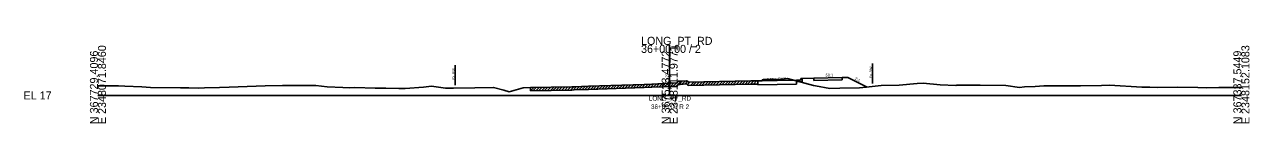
# Model space of a CAD drawing. Extents: x 974 to 2350744, y -10 to 368509.
# Drawn here: x 974.3 to 1402.8, y 990.3 to 1020.4 of the extents above; entities that cross this region are included whole.
import ezdxf

# ---------------------------------------------------------------- set-up
doc = ezdxf.new("R2010")
doc.units = 0
for name, color, linetype in [('RD_GPK_XS_Cell', 7, 'Continuous'), ('RD_XS_Base', 7, 'Continuous'), ('RD_XS_CurbBase', 7, 'Continuous'), ('RD_XS_CurbFront', 7, 'Continuous'), ('RD_XS_CurbTop', 7, 'Continuous'), ('RD_XS_EarthShd', 7, 'Continuous'), ('RD_XS_ExGround', 7, 'Continuous'), ('RD_XS_ExPaveRet', 7, 'Continuous'), ('RD_XS_ExRW', 7, 'Continuous'), ('RD_XS_Pave', 7, 'Continuous'), ('RD_XS_SW', 7, 'Continuous'), ('RD_XS_SWbase', 7, 'Continuous'), ('RD_XS_TieSlope', 7, 'Continuous'), ('RD_XS_TX_Elev_EX', 7, 'Continuous'), ('RD_XS_TX_Slope', 7, 'Continuous'), ('RD_XS_TX_Station', 7, 'Continuous')]:
    doc.layers.add(name, color=color, linetype=linetype)

msp = doc.modelspace()

# ---------------------------------------------------------------- linework, layer by layer
at = {"layer": 'RD_GPK_XS_Cell'}
for p, q in [((1200, 1000), (1200, 1017.61)), ((1000, 1000), (1200, 1000)), ((1200, 1000), (1400, 1000))]:
    msp.add_line(p, q, dxfattribs=at)
at = {"layer": 'RD_XS_Base'}
for p, q in [((1230.85, 1003.68), (1230.85, 1005.08)), ((1230.85, 1003.68), (1244.38, 1003.92)), ((1244.38, 1005.33), (1244.38, 1003.92))]:
    msp.add_line(p, q, dxfattribs=at)
at = {"layer": 'RD_XS_CurbBase'}
for p, q in [((1245.8, 1004.89), (1244.38, 1004.87)), ((1246.38, 1004.89), (1245.8, 1004.89)), ((1246.38, 1005.89), (1246.38, 1004.89))]:
    msp.add_line(p, q, dxfattribs=at)
at = {"layer": 'RD_XS_CurbFront'}
msp.add_line((1244.38, 1004.87), (1244.38, 1005.31), dxfattribs=at)
at = {"layer": 'RD_XS_CurbTop'}
for p, q in [((1244.38, 1005.31), (1245.8, 1005.39)), ((1244.38, 1005.33), (1244.38, 1005.31)), ((1245.8, 1005.39), (1245.88, 1005.89)), ((1245.88, 1005.89), (1246.38, 1005.89))]:
    msp.add_line(p, q, dxfattribs=at)
at = {"layer": 'RD_XS_EarthShd'}
for p, q in [((1246.38, 1005.89), (1250.38, 1006.03)), ((1260.38, 1006.23), (1262.38, 1006.27))]:
    msp.add_line(p, q, dxfattribs=at)
at = {"layer": 'RD_XS_ExGround'}
msp.add_lwpolyline([(1000, 1003.39), (1007.23, 1003.29), (1009.45, 1003.25), (1015.32, 1003.03), (1018.43, 1002.8), (1028.92, 1002.61), (1029.86, 1002.63), (1031.8, 1002.62), (1035.01, 1002.57), (1037.28, 1002.63), (1042.57, 1002.75), (1045.95, 1002.86), (1058.49, 1003.31), (1064.61, 1003.44), (1065.32, 1003.45), (1067.02, 1003.46), (1073.03, 1003.43), (1075.46, 1003.47), (1076.22, 1003.5), (1080.23, 1003.05), (1085.64, 1002.75), (1087.88, 1002.7), (1089.89, 1002.71), (1097, 1002.5), (1100.76, 1002.52), (1105.25, 1002.42), (1107.49, 1002.4), (1113.91, 1002.84), (1116.64, 1003.24), (1120.79, 1002.65), (1121.58, 1002.58), (1124.41, 1002.55), (1131.82, 1002.68), (1138.42, 1002.77), (1142.01, 1001.82), (1143.83, 1001.3), (1148.79, 1002.65), (1151.27, 1002.8), (1165.79, 1003.03), (1166.65, 1003.04), (1171.65, 1003.21), (1191.1, 1003.86), (1193.8, 1003.97), (1198.01, 1004.19), (1200, 1004.29), (1202.61, 1004.42), (1202.76, 1004.77), (1203.11, 1004.92), (1203.72, 1004.98), (1205.93, 1005.14), (1206.28, 1004.99), (1206.43, 1004.64), (1228.45, 1005.05), (1230.85, 1005.08), (1232.35, 1005.08), (1232.5, 1005.44), (1232.85, 1005.59), (1237.51, 1005.59), (1237.85, 1005.59), (1241.27, 1005.87), (1250.37, 1003.49), (1251, 1003.38), (1256.05, 1002.41), (1259.56, 1002.49), (1266.45, 1002.61), (1268.78, 1002.84), (1273.96, 1003.52), (1280.3, 1003.58), (1286.61, 1004.19), (1288.63, 1004.23), (1294.59, 1003.73), (1300.12, 1003.51), (1300.51, 1003.55), (1302, 1003.54), (1308.65, 1003.55), (1317.63, 1003.49), (1322.34, 1002.82), (1324.17, 1002.95), (1327.81, 1003.17), (1330.93, 1003.34), (1336.12, 1003.34), (1340.23, 1003.35), (1343.71, 1003.37), (1351.06, 1003.5), (1353.89, 1003.53), (1365.15, 1002.85), (1367.92, 1002.84), (1370.77, 1002.78), (1377.65, 1002.9), (1384.71, 1002.81), (1387.89, 1002.69), (1392.06, 1002.82), (1399.17, 1002.75), (1400, 1002.73)], dxfattribs=at)
at = {"layer": 'RD_XS_ExPaveRet'}
for p, q in [((1151.27, 1001.65), (1152.43, 1002.81)), ((1151.27, 1001.65), (1151.27, 1002.8)), ((1152.27, 1001.67), (1153.43, 1002.83)), ((1153.27, 1001.68), (1154.43, 1002.85)), ((1154.27, 1001.7), (1155.43, 1002.86)), ((1155.27, 1001.72), (1156.43, 1002.88)), ((1156.27, 1001.73), (1157.43, 1002.89)), ((1157.27, 1001.75), (1158.43, 1002.91)), ((1158.27, 1001.76), (1159.43, 1002.93)), ((1159.27, 1001.78), (1160.43, 1002.94)), ((1160.27, 1001.8), (1161.43, 1002.96)), ((1161.27, 1001.81), (1162.43, 1002.97)), ((1162.27, 1001.83), (1163.43, 1002.99)), ((1163.27, 1001.84), (1164.43, 1003)), ((1164.27, 1001.86), (1165.43, 1003.02)), ((1165.27, 1001.88), (1166.43, 1003.04)), ((1166.27, 1001.89), (1167.45, 1003.07)), ((1167.27, 1001.92), (1168.45, 1003.1)), ((1168.27, 1001.95), (1169.45, 1003.14)), ((1169.27, 1001.99), (1170.45, 1003.17)), ((1170.27, 1002.02), (1171.45, 1003.2)), ((1171.27, 1002.05), (1172.45, 1003.24)), ((1172.27, 1002.09), (1173.45, 1003.27)), ((1173.27, 1002.12), (1174.45, 1003.3)), ((1174.27, 1002.15), (1175.45, 1003.34)), ((1175.27, 1002.19), (1176.45, 1003.37)), ((1176.27, 1002.22), (1177.45, 1003.4)), ((1177.27, 1002.25), (1178.45, 1003.44)), ((1178.27, 1002.29), (1179.45, 1003.47)), ((1179.27, 1002.32), (1180.45, 1003.5)), ((1180.27, 1002.35), (1181.45, 1003.54)), ((1181.27, 1002.39), (1182.45, 1003.57)), ((1182.27, 1002.42), (1183.45, 1003.6)), ((1183.27, 1002.46), (1184.45, 1003.64)), ((1184.27, 1002.49), (1185.45, 1003.67)), ((1185.27, 1002.52), (1186.45, 1003.71)), ((1186.27, 1002.56), (1187.45, 1003.74)), ((1187.27, 1002.59), (1188.45, 1003.77)), ((1188.27, 1002.62), (1189.45, 1003.81)), ((1189.27, 1002.66), (1190.45, 1003.84)), ((1190.27, 1002.69), (1191.46, 1003.87)), ((1191.1, 1002.72), (1193.8, 1002.83)), ((1191.27, 1002.72), (1192.46, 1003.91)), ((1192.27, 1002.76), (1193.46, 1003.95)), ((1193.27, 1002.8), (1194.47, 1004)), ((1193.8, 1002.83), (1198.01, 1003.05)), ((1194.27, 1002.85), (1195.48, 1004.06)), ((1195.27, 1002.9), (1196.48, 1004.11)), ((1196.27, 1002.96), (1197.48, 1004.16)), ((1197.27, 1003.01), (1198.48, 1004.21)), ((1198.01, 1003.05), (1200, 1003.15)), ((1198.27, 1003.06), (1199.47, 1004.26)), ((1199.27, 1003.11), (1200.47, 1004.31)), ((1200, 1003.15), (1202.61, 1003.27)), ((1200.27, 1003.16), (1201.47, 1004.36)), ((1201.27, 1003.21), (1202.47, 1004.41)), ((1202.27, 1003.26), (1204.02, 1005)), ((1202.61, 1003.27), (1202.76, 1003.62)), ((1202.76, 1003.62), (1203.11, 1003.77)), ((1203.11, 1003.77), (1203.72, 1003.84)), ((1203.27, 1003.79), (1204.52, 1005.04)), ((1203.72, 1003.84), (1205.93, 1003.99)), ((1204.27, 1003.88), (1205.5, 1005.11)), ((1205.27, 1003.95), (1206.29, 1004.96)), ((1205.93, 1003.99), (1206.28, 1003.84)), ((1206.27, 1003.85), (1207.07, 1004.65)), ((1206.28, 1003.84), (1206.43, 1003.49)), ((1206.43, 1003.49), (1228.45, 1003.9)), ((1207.27, 1003.51), (1208.43, 1004.67)), ((1208.27, 1003.53), (1209.43, 1004.69)), ((1209.27, 1003.55), (1210.43, 1004.71)), ((1210.27, 1003.57), (1211.43, 1004.73)), ((1211.27, 1003.58), (1212.43, 1004.75)), ((1212.27, 1003.6), (1213.43, 1004.77)), ((1213.27, 1003.62), (1214.43, 1004.79)), ((1214.27, 1003.64), (1215.43, 1004.8)), ((1215.27, 1003.66), (1216.43, 1004.82)), ((1216.27, 1003.68), (1217.43, 1004.84)), ((1217.27, 1003.7), (1218.43, 1004.86)), ((1218.27, 1003.71), (1219.43, 1004.88)), ((1219.27, 1003.73), (1220.43, 1004.9)), ((1220.27, 1003.75), (1221.43, 1004.92)), ((1221.27, 1003.77), (1222.43, 1004.94)), ((1222.27, 1003.79), (1223.43, 1004.95)), ((1223.27, 1003.81), (1224.43, 1004.97)), ((1224.27, 1003.83), (1225.43, 1004.99)), ((1225.27, 1003.84), (1226.43, 1005.01)), ((1226.27, 1003.86), (1227.43, 1005.03)), ((1227.27, 1003.88), (1228.43, 1005.05)), ((1228.27, 1003.9), (1229.43, 1005.06)), ((1228.45, 1003.9), (1230.85, 1003.94)), ((1229.27, 1003.92), (1230.43, 1005.08)), ((1230.85, 1005.08), (1230.85, 1003.94)), ((1151.27, 1001.65), (1165.79, 1001.88)), ((1165.79, 1001.88), (1166.65, 1001.9)), ((1166.65, 1001.9), (1171.65, 1002.07)), ((1171.65, 1002.07), (1191.1, 1002.72))]:
    msp.add_line(p, q, dxfattribs=at)
at = {"layer": 'RD_XS_ExRW'}
for p, q in [((1125, 1003.56), (1125, 1010.56)), ((1271, 1004.13), (1271, 1011.13))]:
    msp.add_line(p, q, dxfattribs=at)
at = {"layer": 'RD_XS_Pave'}
msp.add_line((1230.85, 1005.08), (1244.38, 1005.33), dxfattribs=at)
at = {"layer": 'RD_XS_SW'}
msp.add_line((1250.38, 1006.03), (1260.38, 1006.23), dxfattribs=at)
at = {"layer": 'RD_XS_SWbase'}
for p, q in [((1250.38, 1006.03), (1250.38, 1005.19)), ((1250.38, 1005.19), (1260.38, 1005.39)), ((1260.38, 1005.39), (1260.38, 1006.23))]:
    msp.add_line(p, q, dxfattribs=at)
at = {"layer": 'RD_XS_TieSlope'}
msp.add_line((1262.38, 1006.27), (1269.14, 1002.89), dxfattribs=at)

# ---------------------------------------------------------------- texts
at = {"layer": 'RD_GPK_XS_Cell'}
for s, p in [('LONG_PT_RD', (1190, 1017.61)), ('36+00.00 / 2', (1190, 1014.81)), ('EL 17', (974, 998.6))]:
    msp.add_text(s, height=2.8, dxfattribs=at).set_placement(p)
for s, p in [('E 2348071.8460', (1002.8, 990)), ('E 2348111.9771', (1202.8, 990)), ('E 2348152.1083', (1402.8, 990)), ('N 367729.4096', (1000, 990)), ('N 367533.4772', (1200, 990)), ('N 367337.5449', (1400, 990))]:
    msp.add_text(s, height=2.8, rotation=90, dxfattribs=at).set_placement(p)
at = {"layer": 'RD_XS_ExRW'}
for p in [(1124.75, 1005.51), (1270.75, 1006.08)]:
    msp.add_text('EX. R/W ', height=0.75, rotation=90, dxfattribs=at).set_placement(p)
at = {"layer": 'RD_XS_TX_Elev_EX'}
msp.add_text('21.29', height=1, rotation=90, dxfattribs=at).set_placement((1199.51, 1004.29))
at = {"layer": 'RD_XS_TX_Slope'}
for s, height, rotation, p in [('50:1', 1, 1.1458, (1254.55, 1006.56)), ('MATCH EXIST', 0.75, 1.4994, (1234.01, 1005.29)), ('2:1', 1, 333.4349, (1264.65, 1005.56))]:
    msp.add_text(s, height=height, rotation=rotation, dxfattribs=at).set_placement(p)
at = {"layer": 'RD_XS_TX_Station'}
for s, p in [('LONG_PT_RD', (1192.72, 998.18)), ('36+00.00 R 2', (1193.48, 995.28))]:
    msp.add_text(s, height=1.6, dxfattribs=at).set_placement(p)

doc.saveas('drawing.dxf')
